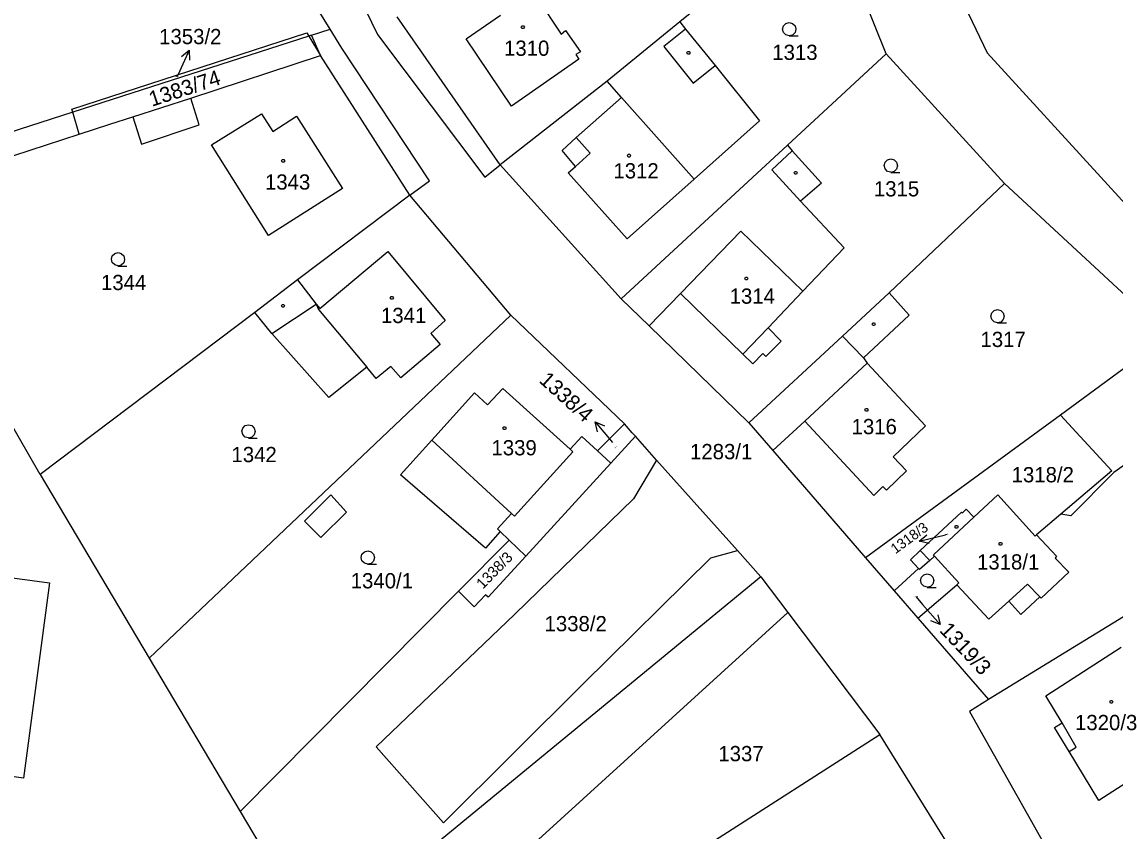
# Model space of a CAD drawing. Extents: x -621797 to -620972, y -1175539 to -1174697.
# Drawn here: x -621620.7 to -621498.7, y -1175452.9 to -1175362.6 of the extents above; entities that cross this region are included whole.
import ezdxf

# ---------------------------------------------------------------- set-up
doc = ezdxf.new("R2010")
doc.units = 0
for name, color, linetype in [('INZ mimo EON - nadz', 7, 'Continuous'), ('Rozvod plynu EON', 7, 'Continuous'), ('SDEL EON', 7, 'Continuous'), ('SDEL EON - popis', 7, 'Continuous'), ('Silnoproud EON', 7, 'Continuous'), ('Silnoproud EON - popis', 7, 'Continuous')]:
    doc.layers.add(name, color=color, linetype=linetype)

msp = doc.modelspace()

# ---------------------------------------------------------------- linework, layer by layer
at = {"layer": 'INZ mimo EON - nadz'}
for p, q in [((-621602.001, -1175365.757), (-621603.26, -1175368.48)), ((-621603.38, -1175368.73), (-621603.26, -1175368.48)), ((-621556.698, -1175407.232), (-621554.77, -1175409.53)), ((-621520.529, -1175420.533), (-621517.61, -1175419.84)), ((-621517.41, -1175419.79), (-621517.61, -1175419.84)), ((-621520.88, -1175426.76), (-621520.16, -1175427.59)), ((-621518.188, -1175429.851), (-621520.16, -1175427.59))]:
    msp.add_line(p, q, dxfattribs=at)
for points in [[(-621602.874, -1175366.455), (-621602.001, -1175365.757), (-621601.967, -1175366.875)], [(-621556.438, -1175408.319), (-621556.698, -1175407.232), (-621555.672, -1175407.676)], [(-621519.44, -1175420.789), (-621520.529, -1175420.533), (-621519.671, -1175419.816)], [(-621518.468, -1175428.768), (-621518.188, -1175429.851), (-621519.222, -1175429.426)]]:
    msp.add_lwpolyline(points, dxfattribs=at)
at = {"layer": 'Rozvod plynu EON'}
for points in [[(-621564.69, -1175363.02), (-621564.6, -1175363.17), (-621564.69, -1175363.32), (-621564.87, -1175363.32), (-621564.96, -1175363.17), (-621564.87, -1175363.02)], [(-621546.2, -1175365.91), (-621546.11, -1175366.06), (-621546.2, -1175366.21), (-621546.38, -1175366.21), (-621546.47, -1175366.06), (-621546.38, -1175365.91)], [(-621591.44, -1175377.96), (-621591.35, -1175378.11), (-621591.44, -1175378.26), (-621591.62, -1175378.26), (-621591.71, -1175378.11), (-621591.62, -1175377.96)], [(-621552.84, -1175377.37), (-621552.75, -1175377.52), (-621552.84, -1175377.67), (-621553.02, -1175377.67), (-621553.11, -1175377.52), (-621553.02, -1175377.37)], [(-621534.24, -1175379.3), (-621534.15, -1175379.45), (-621534.24, -1175379.6), (-621534.42, -1175379.6), (-621534.51, -1175379.45), (-621534.42, -1175379.3)], [(-621539.74, -1175391.08), (-621539.65, -1175391.23), (-621539.74, -1175391.38), (-621539.92, -1175391.38), (-621540.01, -1175391.23), (-621539.92, -1175391.08)], [(-621591.46, -1175394.12), (-621591.37, -1175394.27), (-621591.46, -1175394.42), (-621591.64, -1175394.42), (-621591.73, -1175394.27), (-621591.64, -1175394.12)], [(-621579.31, -1175393.24), (-621579.22, -1175393.39), (-621579.31, -1175393.54), (-621579.49, -1175393.54), (-621579.58, -1175393.39), (-621579.49, -1175393.24)], [(-621525.53, -1175396.16), (-621525.44, -1175396.31), (-621525.53, -1175396.46), (-621525.71, -1175396.46), (-621525.8, -1175396.31), (-621525.71, -1175396.16)], [(-621526.34, -1175405.74), (-621526.25, -1175405.89), (-621526.34, -1175406.04), (-621526.52, -1175406.04), (-621526.61, -1175405.89), (-621526.52, -1175405.74)], [(-621566.73, -1175407.77), (-621566.64, -1175407.92), (-621566.73, -1175408.07), (-621566.91, -1175408.07), (-621567, -1175407.92), (-621566.91, -1175407.77)], [(-621516.28, -1175418.79), (-621516.19, -1175418.94), (-621516.28, -1175419.09), (-621516.46, -1175419.09), (-621516.55, -1175418.94), (-621516.46, -1175418.79)], [(-621511.37, -1175420.7), (-621511.28, -1175420.85), (-621511.37, -1175421), (-621511.55, -1175421), (-621511.64, -1175420.85), (-621511.55, -1175420.7)], [(-621499.01, -1175438.3), (-621498.92, -1175438.45), (-621499.01, -1175438.6), (-621499.19, -1175438.6), (-621499.28, -1175438.45), (-621499.19, -1175438.3)]]:
    msp.add_lwpolyline(points, close=True, dxfattribs=at)
at = {"layer": 'SDEL EON'}
for points in [[(-621535.03, -1175364.14), (-621535.41, -1175364.04), (-621535.68, -1175363.77), (-621535.78, -1175363.4), (-621535.68, -1175363.03), (-621535.41, -1175362.76), (-621535.04, -1175362.66), (-621534.67, -1175362.76), (-621534.4, -1175363.03), (-621534.3, -1175363.41), (-621534.4, -1175363.79), (-621534.67, -1175364.06), (-621535.05, -1175364.16), (-621534.05, -1175364.16)], [(-621523.69, -1175379.37), (-621524.07, -1175379.27), (-621524.34, -1175379), (-621524.44, -1175378.63), (-621524.34, -1175378.26), (-621524.07, -1175377.99), (-621523.7, -1175377.89), (-621523.33, -1175377.99), (-621523.06, -1175378.26), (-621522.96, -1175378.64), (-621523.06, -1175379.02), (-621523.33, -1175379.29), (-621523.71, -1175379.39), (-621522.71, -1175379.39)], [(-621609.95, -1175389.82), (-621610.33, -1175389.72), (-621610.6, -1175389.45), (-621610.7, -1175389.08), (-621610.6, -1175388.71), (-621610.33, -1175388.44), (-621609.96, -1175388.34), (-621609.59, -1175388.44), (-621609.32, -1175388.71), (-621609.22, -1175389.09), (-621609.32, -1175389.47), (-621609.59, -1175389.74), (-621609.97, -1175389.84), (-621608.97, -1175389.84)], [(-621511.79, -1175396.17), (-621512.17, -1175396.07), (-621512.44, -1175395.8), (-621512.54, -1175395.43), (-621512.44, -1175395.06), (-621512.17, -1175394.79), (-621511.8, -1175394.69), (-621511.43, -1175394.79), (-621511.16, -1175395.06), (-621511.06, -1175395.44), (-621511.16, -1175395.82), (-621511.43, -1175396.09), (-621511.81, -1175396.19), (-621510.81, -1175396.19)], [(-621595.39, -1175409.02), (-621595.77, -1175408.92), (-621596.04, -1175408.65), (-621596.14, -1175408.28), (-621596.04, -1175407.91), (-621595.77, -1175407.64), (-621595.4, -1175407.54), (-621595.03, -1175407.64), (-621594.76, -1175407.91), (-621594.66, -1175408.29), (-621594.76, -1175408.67), (-621595.03, -1175408.94), (-621595.41, -1175409.04), (-621594.41, -1175409.04)], [(-621582.08, -1175423.1), (-621582.46, -1175423), (-621582.73, -1175422.73), (-621582.83, -1175422.36), (-621582.73, -1175421.99), (-621582.46, -1175421.72), (-621582.09, -1175421.62), (-621581.72, -1175421.72), (-621581.45, -1175421.99), (-621581.35, -1175422.37), (-621581.45, -1175422.75), (-621581.72, -1175423.02), (-621582.1, -1175423.12), (-621581.1, -1175423.12)], [(-621519.63, -1175425.67), (-621520.01, -1175425.57), (-621520.28, -1175425.3), (-621520.38, -1175424.93), (-621520.28, -1175424.56), (-621520.01, -1175424.29), (-621519.64, -1175424.19), (-621519.27, -1175424.29), (-621519, -1175424.56), (-621518.9, -1175424.94), (-621519, -1175425.32), (-621519.27, -1175425.59), (-621519.65, -1175425.69), (-621518.65, -1175425.69)]]:
    msp.add_lwpolyline(points, dxfattribs=at)
at = {"layer": 'SDEL EON - popis'}
for p, q in [((-621590.25, -1175345.05), (-621580.99, -1175363.99)), ((-621584.98, -1175365.53), (-621586.28, -1175363.42)), ((-621546.62, -1175363.4), (-621549.04, -1175365.35)), ((-621588.35, -1175364.08), (-621588.66, -1175364.18)), ((-621580.99, -1175363.99), (-621569.01, -1175379.92)), ((-621575.21, -1175380.32), (-621584.98, -1175365.53)), ((-621549.04, -1175365.35), (-621545.75, -1175369.43)), ((-621545.75, -1175369.43), (-621543.32, -1175367.46)), ((-621553.77, -1175371.02), (-621545.67, -1175380.14)), ((-621600.89, -1175374.08), (-621601.84, -1175371.11)), ((-621608.29, -1175373.17), (-621607.35, -1175376.23)), ((-621607.35, -1175376.23), (-621600.89, -1175374.08)), ((-621558.81, -1175375.48), (-621557.26, -1175377.26)), ((-621534.7, -1175376.97), (-621537, -1175379.1)), ((-621557.26, -1175377.26), (-621558.9, -1175378.72)), ((-621569.01, -1175379.92), (-621567.3, -1175378.55)), ((-621537, -1175379.1), (-621533.78, -1175382.61)), ((-621577.39, -1175381.92), (-621575.21, -1175380.32)), ((-621540.46, -1175385.94), (-621547.17, -1175392.89)), ((-621533.51, -1175392.64), (-621540.46, -1175385.94)), ((-621592.8, -1175397.35), (-621587.83, -1175394.08)), ((-621587.83, -1175394.08), (-621587.57, -1175394.67)), ((-621587.57, -1175394.67), (-621582.19, -1175401.11)), ((-621537.4, -1175396.72), (-621540.22, -1175399.68)), ((-621529.11, -1175397.65), (-621526.76, -1175400.09)), ((-621526.35, -1175400.67), (-621533.32, -1175407.13)), ((-621574.92, -1175409.25), (-621566.03, -1175417.46)), ((-621565.72, -1175417.74), (-621559.21, -1175410.56)), ((-621559.21, -1175410.56), (-621559.51, -1175410.28)), ((-621589.14, -1175418.29), (-621586.2, -1175415.38)), ((-621586.2, -1175415.38), (-621584.47, -1175417.29)), ((-621584.47, -1175417.29), (-621587.32, -1175420.12)), ((-621587.32, -1175420.12), (-621589.14, -1175418.29)), ((-621566.03, -1175417.46), (-621567.61, -1175419.17)), ((-621566.03, -1175417.46), (-621565.72, -1175417.74)), ((-621567.61, -1175419.17), (-621567.29, -1175419.47)), ((-621519.36, -1175422.7), (-621520.43, -1175421.59)), ((-621538.22, -1175424.5), (-621580, -1175458.85)), ((-621508.46, -1175425.35), (-621510.52, -1175427.23)), ((-621507.06, -1175426.74), (-621508.46, -1175425.35)), ((-621503.02, -1175443.53), (-621504.58, -1175440.79)), ((-621503.79, -1175443.99), (-621503.02, -1175443.53))]:
    msp.add_line(p, q, dxfattribs=at)
at = {"layer": 'Silnoproud EON'}
for p, q in [((-621522.67, -1175345.56), (-621512.96, -1175366.06)), ((-621586.28, -1175363.42), (-621596.02, -1175347.54)), ((-621530.94, -1175349.43), (-621547.26, -1175362.6)), ((-621524.21, -1175366.15), (-621530.94, -1175349.43)), ((-621563.61, -1175359.29), (-621560.49, -1175363.95)), ((-621567.3, -1175378.55), (-621578.8, -1175362.02)), ((-621571.12, -1175364.48), (-621567.27, -1175361.83)), ((-621588.35, -1175364.08), (-621586.28, -1175363.42)), ((-621560.49, -1175363.95), (-621560.03, -1175363.57)), ((-621560.03, -1175363.57), (-621558.34, -1175365.92)), ((-621547.26, -1175362.6), (-621555.35, -1175369.22)), ((-621547.26, -1175362.6), (-621546.62, -1175363.4)), ((-621546.62, -1175363.4), (-621543.32, -1175367.46)), ((-621615.11, -1175372.32), (-621588.87, -1175363.82)), ((-621588.66, -1175364.18), (-621615.01, -1175372.67)), ((-621588.87, -1175363.82), (-621588.66, -1175364.18)), ((-621588.66, -1175364.18), (-621587.37, -1175366.36)), ((-621587.37, -1175366.36), (-621588.35, -1175364.08)), ((-621566.03, -1175371.98), (-621571.12, -1175364.48)), ((-621558.34, -1175365.92), (-621558.86, -1175366.25)), ((-621524.21, -1175366.15), (-621535.25, -1175376.36)), ((-621511.03, -1175380.61), (-621524.21, -1175366.15)), ((-621512.96, -1175366.06), (-621489.46, -1175391.75)), ((-621601.84, -1175371.11), (-621587.37, -1175366.36)), ((-621577.39, -1175381.92), (-621587.37, -1175366.36)), ((-621558.52, -1175366.77), (-621566.03, -1175371.98)), ((-621558.86, -1175366.25), (-621558.52, -1175366.77)), ((-621543.32, -1175367.46), (-621538.37, -1175373.64)), ((-621555.35, -1175369.22), (-621567.3, -1175378.55)), ((-621553.77, -1175371.02), (-621555.35, -1175369.22)), ((-621558.81, -1175375.48), (-621553.77, -1175371.02)), ((-621608.29, -1175373.17), (-621601.84, -1175371.11)), ((-621615.01, -1175372.67), (-621637.81, -1175380.02)), ((-621615.01, -1175372.67), (-621615.11, -1175372.32)), ((-621614.31, -1175375.13), (-621615.01, -1175372.67)), ((-621610.87, -1175374), (-621608.29, -1175373.17)), ((-621599.51, -1175376.33), (-621593.96, -1175372.87)), ((-621593.96, -1175372.87), (-621592.69, -1175374.81)), ((-621592.69, -1175374.81), (-621590.05, -1175373.13)), ((-621590.05, -1175373.13), (-621584.91, -1175381.17)), ((-621614.31, -1175375.13), (-621610.87, -1175374)), ((-621538.37, -1175373.64), (-621545.67, -1175380.14)), ((-621631.78, -1175380.83), (-621614.31, -1175375.13)), ((-621560.39, -1175376.93), (-621558.81, -1175375.48)), ((-621593.15, -1175386.43), (-621599.51, -1175376.33)), ((-621558.9, -1175378.72), (-621560.39, -1175376.93)), ((-621535.25, -1175376.36), (-621553.79, -1175393.51)), ((-621535.25, -1175376.36), (-621534.7, -1175376.97)), ((-621534.7, -1175376.97), (-621531.46, -1175380.59)), ((-621567.3, -1175378.55), (-621553.79, -1175393.51)), ((-621559.73, -1175379.45), (-621558.9, -1175378.72)), ((-621553.13, -1175386.8), (-621559.73, -1175379.45)), ((-621545.67, -1175380.14), (-621553.13, -1175386.8)), ((-621531.46, -1175380.59), (-621533.78, -1175382.61)), ((-621511.03, -1175380.61), (-621523.88, -1175392.81)), ((-621492.72, -1175397.61), (-621511.03, -1175380.61)), ((-621584.91, -1175381.17), (-621593.15, -1175386.43)), ((-621577.39, -1175381.92), (-621589.93, -1175391.39)), ((-621566.11, -1175395.33), (-621577.39, -1175381.92)), ((-621533.78, -1175382.61), (-621528.9, -1175387.81)), ((-621618.63, -1175413.08), (-621634.99, -1175384.89)), ((-621528.9, -1175387.81), (-621533.51, -1175392.64)), ((-621587.44, -1175394.58), (-621579.86, -1175388.22)), ((-621579.86, -1175388.22), (-621573.43, -1175395.93)), ((-621589.93, -1175391.39), (-621594.67, -1175395.01)), ((-621589.93, -1175391.39), (-621587.83, -1175394.08)), ((-621547.17, -1175392.89), (-621550.69, -1175396.52)), ((-621540.22, -1175399.68), (-621547.17, -1175392.89)), ((-621533.51, -1175392.64), (-621537.4, -1175396.72)), ((-621523.88, -1175392.81), (-621529.11, -1175397.65)), ((-621523.88, -1175392.81), (-621521.67, -1175395.33)), ((-621587.83, -1175394.08), (-621587.44, -1175394.58)), ((-621553.79, -1175393.51), (-621550.69, -1175396.52)), ((-621594.67, -1175395.01), (-621618.63, -1175413.08)), ((-621606.47, -1175433.6), (-621566.11, -1175395.33)), ((-621592.8, -1175397.35), (-621594.67, -1175395.01)), ((-621553.44, -1175407.45), (-621566.11, -1175395.33)), ((-621521.67, -1175395.33), (-621526.76, -1175400.09)), ((-621573.43, -1175395.93), (-621575.03, -1175397.36)), ((-621550.69, -1175396.52), (-621539.54, -1175407.34)), ((-621586.43, -1175404.49), (-621592.8, -1175397.35)), ((-621575.03, -1175397.36), (-621573.99, -1175398.59)), ((-621529.11, -1175397.65), (-621539.54, -1175407.34)), ((-621537.4, -1175396.72), (-621535.95, -1175398.21)), ((-621492.72, -1175397.61), (-621504.77, -1175406.46)), ((-621573.99, -1175398.59), (-621578.41, -1175402.32)), ((-621535.95, -1175398.21), (-621537.64, -1175399.92)), ((-621539.09, -1175400.75), (-621540.22, -1175399.68)), ((-621537.98, -1175399.6), (-621539.09, -1175400.75)), ((-621537.64, -1175399.92), (-621537.98, -1175399.6)), ((-621526.76, -1175400.09), (-621526.35, -1175400.67)), ((-621582.19, -1175401.11), (-621586.43, -1175404.49)), ((-621581.13, -1175402.38), (-621582.19, -1175401.11)), ((-621579.5, -1175401.03), (-621581.13, -1175402.38)), ((-621578.41, -1175402.32), (-621579.5, -1175401.03)), ((-621526.35, -1175400.67), (-621519.84, -1175407.65)), ((-621574.92, -1175409.25), (-621570.18, -1175404)), ((-621570.18, -1175404), (-621568.71, -1175405.34)), ((-621568.71, -1175405.34), (-621567.02, -1175403.49)), ((-621567.02, -1175403.49), (-621559.51, -1175410.28)), ((-621488.16, -1175405.34), (-621498.81, -1175412.88)), ((-621556.43, -1175410.47), (-621553.44, -1175407.45)), ((-621552.56, -1175408.44), (-621553.44, -1175407.45)), ((-621539.54, -1175407.34), (-621536.87, -1175410.43)), ((-621533.32, -1175407.13), (-621536.87, -1175410.43)), ((-621525.59, -1175415.43), (-621533.32, -1175407.13)), ((-621504.77, -1175406.46), (-621526.52, -1175422.41)), ((-621519.84, -1175407.65), (-621523.44, -1175411.11)), ((-621504.77, -1175406.46), (-621499.04, -1175412.68)), ((-621559.51, -1175410.28), (-621558.19, -1175408.85)), ((-621558.19, -1175408.85), (-621556.43, -1175410.47)), ((-621552.21, -1175408.83), (-621554.97, -1175411.82)), ((-621552.21, -1175408.83), (-621552.56, -1175408.44)), ((-621549.84, -1175411.49), (-621552.21, -1175408.83)), ((-621578.42, -1175413.13), (-621574.92, -1175409.25)), ((-621554.97, -1175411.82), (-621556.43, -1175410.47)), ((-621536.87, -1175410.43), (-621526.52, -1175422.41)), ((-621523.44, -1175411.11), (-621521.94, -1175412.7)), ((-621554.97, -1175411.82), (-621564.43, -1175422.2)), ((-621549.84, -1175411.49), (-621552.44, -1175415.8)), ((-621540.82, -1175421.59), (-621549.84, -1175411.49)), ((-621618.63, -1175413.08), (-621606.47, -1175433.6)), ((-621568.96, -1175421.3), (-621578.42, -1175413.13)), ((-621521.94, -1175412.7), (-621524.19, -1175414.85)), ((-621499.04, -1175412.68), (-621504.72, -1175417.51)), ((-621498.81, -1175412.88), (-621503.61, -1175417.72)), ((-621524.61, -1175414.44), (-621525.59, -1175415.43)), ((-621524.19, -1175414.85), (-621524.61, -1175414.44)), ((-621552.44, -1175415.8), (-621565.68, -1175428.68)), ((-621514.44, -1175417.87), (-621511.77, -1175415.38)), ((-621511.77, -1175415.38), (-621507.59, -1175419.97)), ((-621520.43, -1175421.59), (-621515.81, -1175417.29)), ((-621515.81, -1175417.29), (-621515.72, -1175417.38)), ((-621515.72, -1175417.38), (-621515.28, -1175416.98)), ((-621515.28, -1175416.98), (-621514.44, -1175417.87)), ((-621518.96, -1175422.07), (-621514.44, -1175417.87)), ((-621504.72, -1175417.51), (-621507.46, -1175419.84)), ((-621503.61, -1175417.72), (-621504.72, -1175417.51)), ((-621567.29, -1175419.47), (-621568.96, -1175421.3)), ((-621566.3, -1175420.42), (-621567.29, -1175419.47)), ((-621507.59, -1175419.97), (-621507.46, -1175419.84)), ((-621507.46, -1175419.84), (-621505.21, -1175422.21)), ((-621571.96, -1175426.13), (-621566.3, -1175420.42)), ((-621566.3, -1175420.42), (-621564.43, -1175422.2)), ((-621564.43, -1175422.2), (-621568.66, -1175426.8)), ((-621543.8, -1175422.4), (-621540.82, -1175421.59)), ((-621538.22, -1175424.5), (-621540.82, -1175421.59)), ((-621521.52, -1175422.6), (-621520.43, -1175421.59)), ((-621518.83, -1175422.22), (-621519.36, -1175422.7)), ((-621518.83, -1175422.22), (-621518.96, -1175422.07)), ((-621516.12, -1175425.2), (-621518.83, -1175422.22)), ((-621505.21, -1175422.21), (-621505.35, -1175422.42)), ((-621633.64, -1175423.05), (-621617.59, -1175425.2)), ((-621558.06, -1175436.47), (-621543.8, -1175422.4)), ((-621526.52, -1175422.41), (-621523.34, -1175426.07)), ((-621520.6, -1175423.57), (-621521.52, -1175422.6)), ((-621519.36, -1175422.7), (-621520.49, -1175423.69)), ((-621505.35, -1175422.42), (-621503.85, -1175423.99)), ((-621538.22, -1175424.5), (-621535.21, -1175428.49)), ((-621520.6, -1175423.57), (-621523.34, -1175426.07)), ((-621520.49, -1175423.69), (-621520.6, -1175423.57)), ((-621503.85, -1175423.99), (-621506.92, -1175426.88)), ((-621617.59, -1175425.2), (-621620.51, -1175446.98)), ((-621520.7, -1175429.11), (-621516.32, -1175425.4)), ((-621516.32, -1175425.4), (-621516.12, -1175425.2)), ((-621512.75, -1175429.25), (-621516.32, -1175425.4)), ((-621596.31, -1175450.69), (-621571.96, -1175426.13)), ((-621570.19, -1175427.88), (-621571.96, -1175426.13)), ((-621568.96, -1175426.53), (-621570.19, -1175427.88)), ((-621568.66, -1175426.8), (-621568.96, -1175426.53)), ((-621523.34, -1175426.07), (-621520.7, -1175429.11)), ((-621492.9, -1175426.01), (-621512.82, -1175438.21)), ((-621507.06, -1175426.74), (-621509.21, -1175428.73)), ((-621506.92, -1175426.88), (-621507.06, -1175426.74)), ((-621510.52, -1175427.23), (-621512.75, -1175429.25)), ((-621509.21, -1175428.73), (-621510.52, -1175427.23)), ((-621565.68, -1175428.68), (-621581.15, -1175443.49)), ((-621535.21, -1175428.49), (-621563.01, -1175453.81)), ((-621535.21, -1175428.49), (-621524.95, -1175442.09)), ((-621520.7, -1175429.11), (-621512.82, -1175438.21)), ((-621506.4, -1175437.81), (-621497.99, -1175432.37)), ((-621606.47, -1175433.6), (-621596.31, -1175450.69)), ((-621573.63, -1175451.97), (-621558.06, -1175436.47)), ((-621504.58, -1175440.79), (-621506.4, -1175437.81)), ((-621512.82, -1175438.21), (-621514.93, -1175439.55)), ((-621514.93, -1175439.55), (-621505.14, -1175456.86)), ((-621505.43, -1175441.31), (-621504.58, -1175440.79)), ((-621503.79, -1175443.99), (-621505.43, -1175441.31)), ((-621544.32, -1175454.53), (-621524.95, -1175442.09)), ((-621513.2, -1175460.94), (-621524.95, -1175442.09)), ((-621581.15, -1175443.49), (-621573.63, -1175451.97)), ((-621500.5, -1175449.46), (-621503.79, -1175443.99)), ((-621491.16, -1175443.51), (-621500.5, -1175449.46)), ((-621620.51, -1175446.98), (-621636.56, -1175444.83)), ((-621596.31, -1175450.69), (-621592.82, -1175456.58))]:
    msp.add_line(p, q, dxfattribs=at)

# ---------------------------------------------------------------- texts
at = {"layer": 'INZ mimo EON - nadz'}
for s, p in [('1353/2', (-621605.369, -1175365.08)), ('1283/1', (-621546.117, -1175411.39))]:
    msp.add_text(s, height=1.7, dxfattribs=at).set_placement(p)
for s, height, rotation, p in [('1338/4', 1.7, 317.99158, (-621563.058, -1175402.733)), ('1318/3', 1.14, 36.21093, (-621523.193, -1175422.007)), ('1319/3', 1.7, 313.23603, (-621518.356, -1175430.557))]:
    msp.add_text(s, height=height, rotation=rotation, dxfattribs=at).set_placement(p)
at = {"layer": 'Silnoproud EON - popis'}
for s, height, p in [('1310', 1.7, (-621566.877, -1175366.38)), ('1313', 1.7, (-621536.937, -1175366.84)), ('1353/2', 0.1, (-621603.619, -1175368.73)), ('1312', 1.7, (-621554.667, -1175380.06)), ('1343', 1.7, (-621593.557, -1175381.31)), ('1315', 1.7, (-621525.597, -1175382.07)), ('1344', 1.7, (-621611.857, -1175392.52)), ('1314', 1.7, (-621541.697, -1175394.04)), ('1341', 1.7, (-621580.607, -1175396.2)), ('1317', 1.7, (-621513.697, -1175398.87)), ('1316', 1.7, (-621528.087, -1175408.6)), ('1342', 1.7, (-621597.297, -1175411.72)), ('1339', 1.7, (-621568.277, -1175410.96)), ('1318/2', 1.7, (-621510.224, -1175413.97)), ('1318/3', 0.1, (-621517.623, -1175419.79)), ('1318/1', 1.7, (-621514.087, -1175423.7)), ('1340/1', 1.7, (-621583.987, -1175425.8)), ('1319/3', 0.1, (-621521.092, -1175426.76)), ('1338/2', 1.7, (-621562.357, -1175430.59)), ('1320/3', 1.7, (-621503.149, -1175441.62)), ('1337', 1.7, (-621542.957, -1175445.09))]:
    msp.add_text(s, height=height, dxfattribs=at).set_placement(p)
for s, height, rotation, p in [('1383/74', 1.7, 18.04817, (-621606.177, -1175372.073)), ('1338/4', 0.1, 47.72738, (-621554.514, -1175410.263)), ('1338/3', 1.2, 45.66474, (-621569.236, -1175425.952))]:
    msp.add_text(s, height=height, rotation=rotation, dxfattribs=at).set_placement(p)

doc.saveas('drawing.dxf')
